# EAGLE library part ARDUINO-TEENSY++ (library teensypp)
Teensy ++ Original Design by Mark Gross Modified Design by Tamir Emran Licensed Under Creative Commons Attribution-ShareAlike 3.0 Unported (CC BY-SA 3.0)
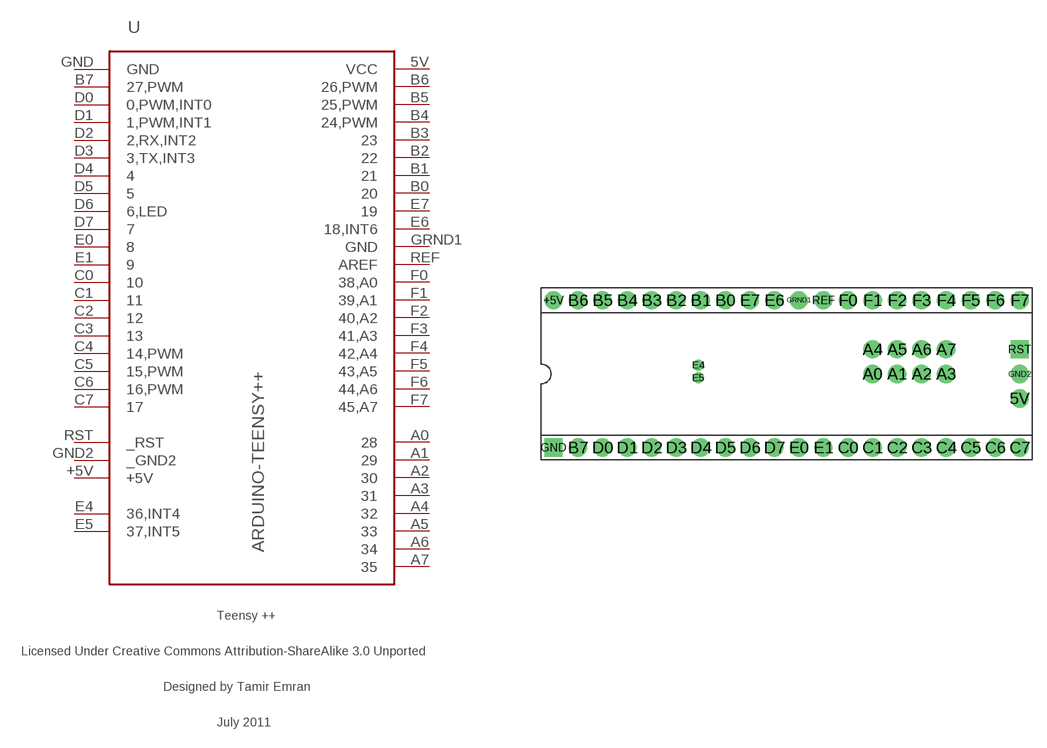
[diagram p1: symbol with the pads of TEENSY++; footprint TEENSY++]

Designator prefix -

## ARDUINO-TEENSY++  [TEENSY++]
5V  VCC  pwr
+5V  +5V  pwr
A0  28
A1  29
A2  30
A3  31
A4  32
A5  33
A6  34
A7  35
B0  20
B1  21
B2  22
B3  23
B4  24,PWM
B5  25,PWM
B6  26,PWM
B7  27,PWM
C0  10
C1  11
C2  12
C3  13
C4  14,PWM
C5  15,PWM
C6  16,PWM
C7  17
D0  0,PWM,INT0
D1  1,PWM,INT1
D2  2,RX,INT2
D3  3,TX,INT3
D4  4
D5  5
D6  6,LED
D7  7
E0  8
E1  9
E4  36,INT4
E5  37,INT5
E6  18,INT6
E7  19
F0  38,A0
F1  39,A1
F2  40,A2
F3  41,A3
F4  42,A4
F5  43,A5
F6  44,A6
F7  45,A7
GND  GND  pwr
GND2  _GND2  pwr
GRND1  GND  pwr
REF  AREF  in
RST  _RST  in

## Footprint TEENSY++ (pad centres in mm)
teensy ++
drill 1.016 pad 1.88 round: 5V 24.13,-2.54; +5V -24.13,7.62; A0 8.89,0; A1 11.43,0; A2 13.97,0; A3 16.51,0; A4 8.89,2.54; A5 11.43,2.54; A6 13.97,2.54; A7 16.51,2.54; B0 -6.35,7.62; B1 -8.89,7.62; B2 -11.43,7.62; B3 -13.97,7.62; B4 -16.51,7.62; B5 -19.05,7.62; B6 -21.59,7.62; B7 -21.59,-7.62; C0 6.35,-7.62; C1 8.89,-7.62; C2 11.43,-7.62; C3 13.97,-7.62; C4 16.51,-7.62; C5 19.05,-7.62; C6 21.59,-7.62; C7 24.13,-7.62; D0 -19.05,-7.62; D1 -16.51,-7.62; D2 -13.97,-7.62; D3 -11.43,-7.62; D4 -8.89,-7.62; D5 -6.35,-7.62; D6 -3.81,-7.62; D7 -1.27,-7.62; E0 1.27,-7.62; E1 3.81,-7.62; E6 -1.27,7.62; E7 -3.81,7.62; F0 6.35,7.62; F1 8.89,7.62; F2 11.43,7.62; F3 13.97,7.62; F4 16.51,7.62; F5 19.05,7.62; F6 21.59,7.62; F7 24.13,7.62; GND2 24.13,0; GRND1 1.27,7.62; REF 3.81,7.62
drill 0.635 pad 1.067 round: E4 -9.144,0.914; E5 -9.144,-0.406
drill 1.016 pad 1.88 square: GND -24.13,-7.62; RST 24.13,2.54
